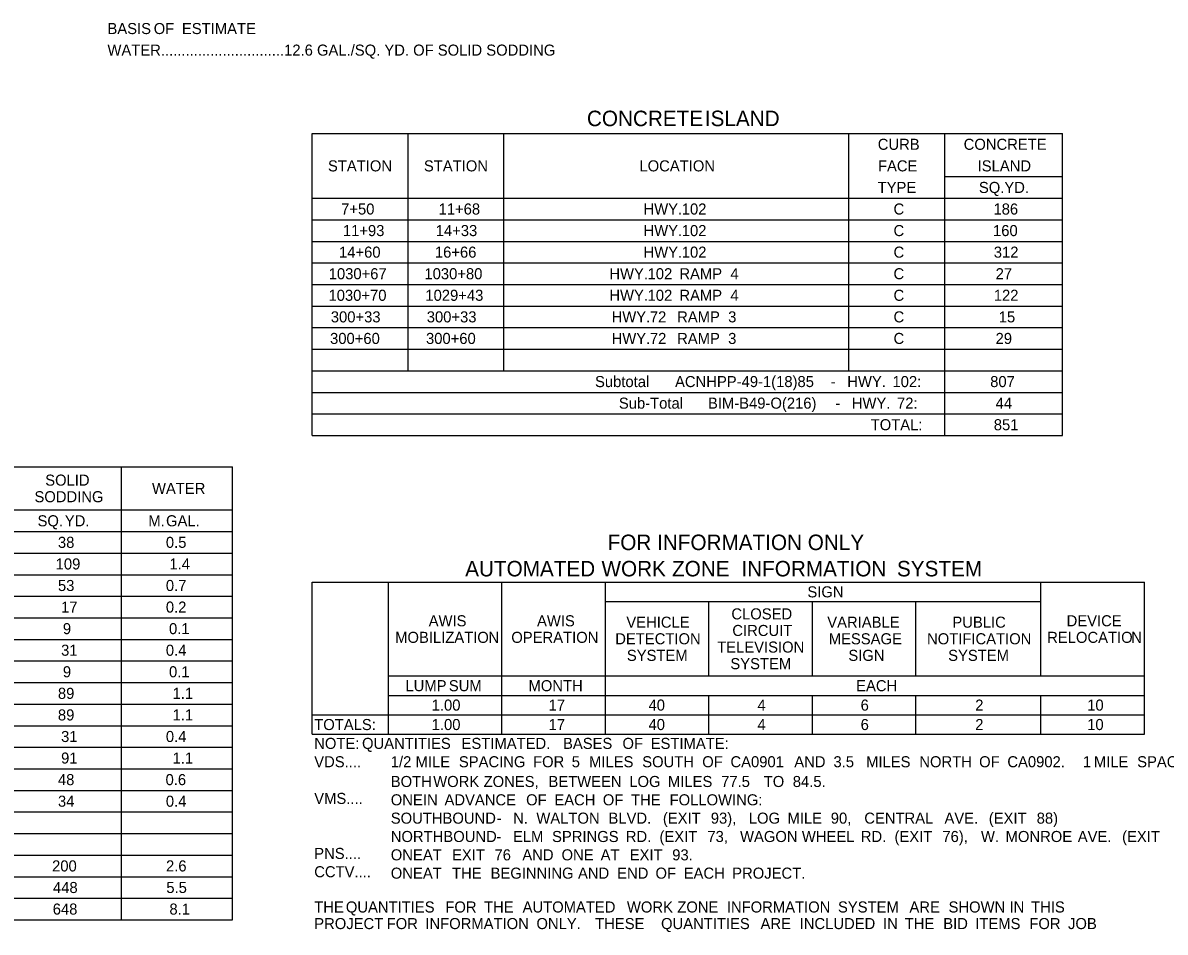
# Model space of a CAD drawing. Extents: x 1226605 to 1228152, y 151309 to 152316.
# Drawn here: x 1227104 to 1227621, y 151407 to 151818 of the extents above; entities that cross this region are included whole.
import ezdxf

# ---------------------------------------------------------------- set-up
doc = ezdxf.new("R2010")
doc.units = 0
doc.layers.add('R_Dimension', color=7, linetype='Continuous')

msp = doc.modelspace()

# ---------------------------------------------------------------- linework, layer by layer
at = {"layer": 'R_Dimension'}
for p, q in [((1227234.9, 151767.85), (1227574.2, 151767.85)), ((1227234.9, 151631.35), (1227234.9, 151767.85)), ((1227278.28, 151660.6), (1227278.28, 151767.85)), ((1227321.67, 151660.6), (1227321.67, 151767.85)), ((1227477.67, 151660.6), (1227477.67, 151767.85)), ((1227521.06, 151631.35), (1227521.06, 151767.85)), ((1227574.2, 151631.35), (1227574.2, 151767.85)), ((1227521.06, 151748.35), (1227574.2, 151748.35)), ((1227234.9, 151738.6), (1227574.2, 151738.6)), ((1227234.9, 151728.85), (1227574.2, 151728.85)), ((1227234.9, 151719.1), (1227574.2, 151719.1)), ((1227234.9, 151709.35), (1227574.2, 151709.35)), ((1227234.9, 151699.6), (1227574.2, 151699.6)), ((1227234.9, 151689.85), (1227574.2, 151689.85)), ((1227234.9, 151680.1), (1227574.2, 151680.1)), ((1227234.9, 151670.35), (1227574.2, 151670.35)), ((1227234.9, 151660.6), (1227574.2, 151660.6)), ((1227234.9, 151650.85), (1227574.2, 151650.85)), ((1227234.9, 151641.1), (1227574.2, 151641.1)), ((1227234.9, 151631.35), (1227574.2, 151631.35)), ((1226605.2, 151617.18), (1227198.97, 151617.18)), ((1227148.76, 151412.43), (1227148.76, 151617.18)), ((1227198.97, 151412.43), (1227198.97, 151617.18)), ((1226844.56, 151597.68), (1227198.97, 151597.68)), ((1227098.55, 151597.68), (1227198.97, 151597.68)), ((1226605.2, 151587.93), (1227198.97, 151587.93)), ((1226605.2, 151578.18), (1227198.97, 151578.18)), ((1226605.2, 151568.43), (1227198.97, 151568.43)), ((1227234.9, 151565.06), (1227611.25, 151565.06)), ((1227234.9, 151496.33), (1227234.9, 151565.06)), ((1227269.51, 151496.33), (1227269.51, 151565.06)), ((1227320.7, 151496.33), (1227320.7, 151565.06)), ((1227367.5, 151496.33), (1227367.5, 151565.06)), ((1227564.45, 151522.65), (1227564.45, 151565.06)), ((1227611.25, 151496.33), (1227611.25, 151565.06)), ((1226605.2, 151558.68), (1227198.97, 151558.68)), ((1227367.5, 151556.29), (1227564.45, 151556.29)), ((1227414.3, 151522.65), (1227414.3, 151556.29)), ((1227461.1, 151522.65), (1227461.1, 151556.29)), ((1227507.9, 151522.65), (1227507.9, 151556.29)), ((1226605.2, 151548.93), (1227198.97, 151548.93)), ((1226605.2, 151539.18), (1227198.97, 151539.18)), ((1226605.2, 151529.43), (1227198.97, 151529.43)), ((1227269.51, 151522.65), (1227611.25, 151522.65)), ((1227564.45, 151522.65), (1227611.25, 151522.65)), ((1226605.2, 151519.68), (1227198.97, 151519.68)), ((1227269.51, 151513.88), (1227611.25, 151513.88)), ((1227414.3, 151496.33), (1227414.3, 151513.88)), ((1227461.1, 151496.33), (1227461.1, 151513.88)), ((1227507.9, 151496.33), (1227507.9, 151513.88)), ((1227564.45, 151496.33), (1227564.45, 151513.88)), ((1226605.2, 151509.93), (1227198.97, 151509.93)), ((1227234.9, 151505.1), (1227611.25, 151505.1)), ((1226605.2, 151500.18), (1227198.97, 151500.18)), ((1227234.9, 151496.33), (1227611.25, 151496.33)), ((1226605.2, 151490.43), (1227198.97, 151490.43)), ((1226605.2, 151480.68), (1227198.97, 151480.68)), ((1226605.2, 151470.93), (1227198.97, 151470.93)), ((1226605.2, 151461.18), (1227198.97, 151461.18)), ((1226605.2, 151451.43), (1227198.97, 151451.43)), ((1226605.2, 151441.68), (1227198.97, 151441.68)), ((1226605.2, 151431.93), (1227198.97, 151431.93)), ((1226605.2, 151422.18), (1227198.97, 151422.18)), ((1226605.2, 151412.43), (1227198.97, 151412.43))]:
    msp.add_line(p, q, dxfattribs=at)

# ---------------------------------------------------------------- texts
for s, height, p in [('BASIS', 5, (1227142.38, 151812.79)), (' OF', 5, (1227161.44, 151812.79)), (' ESTIMATE', 5, (1227174.19, 151812.79)), ('WATER..............................12.6 GAL./SQ. YD. OF SOLID SODDING', 5, (1227142.38, 151803.04)), ('CONCRETE', 7, (1227359.18, 151771.17)), (' ISLAND', 7, (1227409.89, 151771.17)), ('CURB', 5, (1227490.68, 151760.47)), ('CONCRETE', 5, (1227529.52, 151760.47)), ('STATION', 5, (1227242.08, 151750.72)), ('STATION', 5, (1227285.47, 151750.72)), ('LOCATION', 5, (1227382.92, 151750.72)), ('FACE', 5, (1227490.78, 151750.72)), ('ISLAND', 5, (1227535.84, 151750.72)), ('TYPE', 5, (1227490.62, 151740.97)), ('SQ.YD.', 5, (1227536.41, 151740.97)), ('7+50', 5, (1227248.03, 151731.22)), ('11+68', 5, (1227292.1, 151731.22)), ('HWY.', 5, (1227384.77, 151731.22)), (' 102', 5, (1227400.2, 151731.22)), ('C', 5, (1227497.81, 151731.22)), ('186', 5, (1227543, 151731.22)), ('11+93', 5, (1227248.83, 151721.47)), ('14+33', 5, (1227290.8, 151721.47)), ('HWY.', 5, (1227384.77, 151721.47)), (' 102', 5, (1227400.2, 151721.47)), ('C', 5, (1227497.81, 151721.47)), ('160', 5, (1227542.8, 151721.47)), ('14+60', 5, (1227247.08, 151711.72)), ('16+66', 5, (1227290.43, 151711.72)), ('HWY.', 5, (1227384.77, 151711.72)), (' 102', 5, (1227400.2, 151711.72)), ('C', 5, (1227497.81, 151711.72)), ('312', 5, (1227543.14, 151711.72)), ('1030+67', 5, (1227242.42, 151701.97)), ('1030+80', 5, (1227285.7, 151701.97)), ('HWY.', 5, (1227369.32, 151701.97)), (' 102', 5, (1227384.75, 151701.97)), (' RAMP', 5, (1227399.12, 151701.97)), (' 4', 5, (1227422.19, 151701.97)), ('C', 5, (1227497.81, 151701.97)), ('27', 5, (1227543.97, 151701.97)), ('1030+70', 5, (1227242.32, 151692.22)), ('1029+43', 5, (1227286.12, 151692.22)), ('HWY.', 5, (1227369.32, 151692.22)), (' 102', 5, (1227384.75, 151692.22)), (' RAMP', 5, (1227399.12, 151692.22)), (' 4', 5, (1227422.19, 151692.22)), ('C', 5, (1227497.81, 151692.22)), ('122', 5, (1227543.14, 151692.22)), ('300+33', 5, (1227243.36, 151682.47)), ('300+33', 5, (1227286.75, 151682.47)), (' 72', 5, (1227385.77, 151682.47)), (' 3', 5, (1227421.17, 151682.47)), ('C', 5, (1227497.81, 151682.47)), ('HWY.', 5, (1227370.34, 151682.47)), (' RAMP', 5, (1227398.1, 151682.47)), ('15', 5, (1227545.38, 151682.47)), ('300+60', 5, (1227243.03, 151672.72)), ('300+60', 5, (1227286.41, 151672.72)), ('HWY.', 5, (1227370.34, 151672.72)), (' 72', 5, (1227385.77, 151672.72)), (' RAMP', 5, (1227398.1, 151672.72)), (' 3', 5, (1227421.17, 151672.72)), ('C', 5, (1227497.81, 151672.72)), ('29', 5, (1227543.95, 151672.72)), ('Subtotal', 5, (1227362.83, 151653.22)), (' ACNHPP-49-1(18)85', 5, (1227397.16, 151653.22)), (' HWY.', 5, (1227475.04, 151653.22)), (' 102:', 5, (1227495.47, 151653.22)), ('807', 5, (1227541.52, 151653.22)), (' -', 5, (1227467.6, 151653.22)), ('Sub-Total', 5, (1227373.62, 151643.47)), (' BIM-B49-O(216)', 5, (1227412.05, 151643.47)), (' HWY.', 5, (1227477.09, 151643.47)), (' 72:', 5, (1227497.52, 151643.47)), ('44', 5, (1227543.97, 151643.47)), (' -', 5, (1227469.64, 151643.47)), ('TOTAL:', 5, (1227487.48, 151633.72)), ('851', 5, (1227543.14, 151633.72)), ('SOLID', 5, (1227114.23, 151608.68)), ('SODDING', 5, (1227109.38, 151601.18)), ('WATER', 5, (1227162.51, 151604.93)), ('SQ.', 5, (1227110.76, 151590.3)), (' YD.', 5, (1227121.23, 151590.3)), ('M.', 5, (1227160.86, 151590.3)), (' GAL.', 5, (1227167, 151590.3)), ('38', 5, (1227119.99, 151580.55)), ('0.5', 5, (1227168.79, 151580.55)), ('FOR INFORMATION ONLY', 7, (1227368.54, 151579.55)), ('109', 5, (1227118.95, 151570.8)), ('1.4', 5, (1227170.4, 151570.8)), ('AUTOMATED', 7, (1227304.13, 151567.66)), (' WORK', 7, (1227363.16, 151567.66)), (' ZONE', 7, (1227395.07, 151567.66)), (' INFORMATION', 7, (1227426.43, 151567.66)), (' SYSTEM', 7, (1227496.76, 151567.66)), ('53', 5, (1227119.99, 151561.05)), ('0.7', 5, (1227168.79, 151561.05)), ('SIGN', 5, (1227458.86, 151558.18)), ('17', 5, (1227121.41, 151551.3)), ('0.2', 5, (1227168.79, 151551.3)), ('CLOSED', 5, (1227424.49, 151548.22)), ('AWIS', 5, (1227287.62, 151545.11)), ('AWIS', 5, (1227336.61, 151545.11)), ('VEHICLE', 5, (1227377, 151544.47)), ('VARIABLE', 5, (1227467.84, 151544.47)), ('PUBLIC', 5, (1227524.42, 151544.47)), ('DEVICE', 5, (1227576.07, 151545.11)), ('9', 5, (1227122.22, 151541.55)), ('0.1', 5, (1227170.21, 151541.55)), ('CIRCUIT', 5, (1227424.92, 151540.72)), ('MOBILIZATIO', 5, (1227272.46, 151537.61)), ('N', 5, (1227314.63, 151537.61)), ('OPERATION', 5, (1227324.98, 151537.61)), ('DETECTION', 5, (1227371.98, 151536.97)), ('TELEVISION', 5, (1227418.07, 151533.22)), ('MESSAGE', 5, (1227468.51, 151536.97)), ('NOTIFICATION', 5, (1227512.96, 151536.97)), ('RELOCATIO', 5, (1227567.29, 151537.61)), ('N', 5, (1227605.29, 151537.61)), ('31', 5, (1227121.41, 151531.8)), ('0.4', 5, (1227168.79, 151531.8)), ('SYSTEM', 5, (1227377.23, 151529.47)), ('SIGN', 5, (1227477.39, 151529.47)), ('SYSTEM', 5, (1227522.51, 151529.47)), ('SYSTEM', 5, (1227424.03, 151525.72)), ('9', 5, (1227122.22, 151522.05)), ('0.1', 5, (1227170.21, 151522.05)), ('89', 5, (1227119.97, 151512.3)), ('1.1', 5, (1227171.82, 151512.3)), ('LUMP', 5, (1227277.11, 151515.76)), (' SUM', 5, (1227294.87, 151515.76)), ('MONTH', 5, (1227332.76, 151515.76)), ('EACH', 5, (1227480.91, 151515.76)), ('1.00', 5, (1227288.98, 151506.99)), ('17', 5, (1227341.85, 151506.99)), ('40', 5, (1227387.02, 151506.99)), ('4', 5, (1227436.28, 151506.99)), ('6', 5, (1227482.94, 151506.99)), ('2', 5, (1227534.75, 151506.99)), ('10', 5, (1227585.38, 151506.99)), ('89', 5, (1227119.97, 151502.55)), ('1.1', 5, (1227171.82, 151502.55)), ('TOTALS:', 5, (1227235.87, 151498.21)), ('1.00', 5, (1227288.98, 151498.21)), ('17', 5, (1227341.85, 151498.21)), ('40', 5, (1227387.02, 151498.21)), ('4', 5, (1227436.28, 151498.21)), ('6', 5, (1227482.94, 151498.21)), ('2', 5, (1227534.75, 151498.21)), ('10', 5, (1227585.38, 151498.21)), ('31', 5, (1227121.41, 151492.8)), ('0.4', 5, (1227168.79, 151492.8)), ('NOTE:', 5, (1227235.87, 151489.68)), (' QUANTITIES', 5, (1227255.63, 151489.68)), (' ESTIMATED.', 5, (1227300.63, 151489.68)), (' BASES', 5, (1227346.5, 151489.68)), (' OF', 5, (1227373.39, 151489.68)), (' ESTIMATE:', 5, (1227386.15, 151489.68)), ('91', 5, (1227121.41, 151483.05)), ('1.1', 5, (1227171.82, 151483.05)), ('VDS....', 5, (1227235.87, 151481.39)), ('1/2', 5, (1227270.48, 151481.39)), (' MILE', 5, (1227279.85, 151481.39)), (' SPACING', 5, (1227299.42, 151481.39)), (' FOR', 5, (1227332.96, 151481.39)), (' 5', 5, (1227350.44, 151481.39)), (' MILES', 5, (1227358.28, 151481.39)), (' SOUTH', 5, (1227382.33, 151481.39)), (' OF', 5, (1227409.46, 151481.39)), (' CA0901', 5, (1227422.22, 151481.39)), (' AND', 5, (1227451.07, 151481.39)), (' 3.5', 5, (1227468.79, 151481.39)), (' MILES', 5, (1227483.55, 151481.39)), (' NORTH', 5, (1227507.61, 151481.39)), (' OF', 5, (1227534.66, 151481.39)), (' CA0902.', 5, (1227547.41, 151481.39)), (' 1', 5, (1227581.55, 151481.39)), (' MILE', 5, (1227586.55, 151481.39)), (' SPACING', 5, (1227606.11, 151481.39)), ('48', 5, (1227119.99, 151473.3)), ('0.6', 5, (1227168.65, 151473.3)), ('BOTH', 5, (1227270.48, 151472.46)), (' WORK', 5, (1227287.81, 151472.46)), (' ZONES,', 5, (1227310.6, 151472.46)), (' BETWEEN', 5, (1227339.93, 151472.46)), (' LOG', 5, (1227376.47, 151472.46)), (' MILES', 5, (1227393.95, 151472.46)), (' 77.5', 5, (1227418, 151472.46)), (' TO', 5, (1227437.25, 151472.46)), (' 84.5.', 5, (1227450.4, 151472.46)), ('34', 5, (1227119.99, 151463.55)), ('0.4', 5, (1227168.79, 151463.55)), ('VMS....', 5, (1227235.87, 151464.82)), ('ONE', 5, (1227270.48, 151464.18)), (' IN', 5, (1227283.16, 151464.18)), (' ADVANCE', 5, (1227292.92, 151464.18)), (' OF', 5, (1227329.81, 151464.18)), (' EACH', 5, (1227342.57, 151464.18)), (' OF', 5, (1227364.5, 151464.18)), (' THE', 5, (1227377.25, 151464.18)), (' FOLLOWING:', 5, (1227394.7, 151464.18)), ('SOUTHBOUND', 5, (1227270.48, 151455.89)), (' N.', 5, (1227323.95, 151455.89)), (' WALTON', 5, (1227334.46, 151455.89)), (' BLVD.', 5, (1227367.06, 151455.89)), (' (EXIT', 5, (1227391.66, 151455.89)), (' 93),', 5, (1227413.32, 151455.89)), (' LOG', 5, (1227430.52, 151455.89)), (' MILE', 5, (1227448, 151455.89)), (' 90,', 5, (1227467.57, 151455.89)), (' CENTRAL', 5, (1227482.73, 151455.89)), (' AVE.', 5, (1227518.99, 151455.89)), (' (EXIT', 5, (1227539.03, 151455.89)), (' 88)', 5, (1227560.68, 151455.89)), (' -', 5, (1227316.51, 151455.89)), ('NORTHBOUND', 5, (1227270.48, 151447.6)), (' ELM', 5, (1227323.87, 151447.6)), (' SPRINGS', 5, (1227341.55, 151447.6)), (' RD.', 5, (1227374.89, 151447.6)), (' (EXIT', 5, (1227390.13, 151447.6)), (' 73,', 5, (1227411.78, 151447.6)), (' WAGON', 5, (1227426.55, 151447.6)), (' WHEEL', 5, (1227454.5, 151447.6)), (' RD.', 5, (1227481.15, 151447.6)), (' (EXIT', 5, (1227496.39, 151447.6)), (' 76),', 5, (1227518.04, 151447.6)), (' W.', 5, (1227535.48, 151447.6)), (' MONROE', 5, (1227546.62, 151447.6)), (' AVE.', 5, (1227579.26, 151447.6)), (' (EXIT', 5, (1227599.3, 151447.6)), ('PNS....', 5, (1227235.87, 151439.96)), (' -', 5, (1227316.43, 151447.6)), ('ONE', 5, (1227270.48, 151439.31)), (' AT', 5, (1227283.16, 151439.31)), (' EXIT', 5, (1227296.31, 151439.31)), (' 76', 5, (1227315.52, 151439.31)), (' AND', 5, (1227328.12, 151439.31)), (' ONE', 5, (1227345.84, 151439.31)), (' AT', 5, (1227363.51, 151439.31)), (' EXIT', 5, (1227376.66, 151439.31)), (' 93.', 5, (1227395.88, 151439.31)), ('200', 5, (1227117.34, 151434.3)), ('2.6', 5, (1227168.85, 151434.3)), ('CCTV....', 5, (1227235.87, 151431.67)), ('ONE', 5, (1227270.48, 151431.03)), (' AT', 5, (1227283.16, 151431.03)), (' THE', 5, (1227296.31, 151431.03)), (' BEGINNING', 5, (1227313.75, 151431.03)), (' AND', 5, (1227353.28, 151431.03)), (' END', 5, (1227370.99, 151431.03)), (' OF', 5, (1227388.32, 151431.03)), (' EACH', 5, (1227401.07, 151431.03)), (' PROJECT.', 5, (1227423, 151431.03)), ('448', 5, (1227117.75, 151424.55)), ('5.5', 5, (1227168.99, 151424.55)), ('648', 5, (1227117.63, 151414.8)), ('8.1', 5, (1227170.4, 151414.8)), ('THE', 5, (1227235.87, 151415.74)), (' QUANTITIES', 5, (1227248.31, 151415.74)), (' FOR', 5, (1227293.31, 151415.74)), (' THE', 5, (1227310.79, 151415.74)), (' AUTOMATED', 5, (1227328.23, 151415.74)), (' WORK', 5, (1227375.4, 151415.74)), (' ZONE', 5, (1227398.19, 151415.74)), (' INFORMATION', 5, (1227420.59, 151415.74)), (' SYSTEM', 5, (1227470.83, 151415.74)), (' ARE', 5, (1227503.15, 151415.74)), (' SHOWN', 5, (1227520.83, 151415.74)), (' IN', 5, (1227548.39, 151415.74)), (' THIS', 5, (1227558.15, 151415.74)), ('PROJECT', 5, (1227235.87, 151408.24)), (' FOR', 5, (1227266.78, 151408.24)), (' INFORMATION', 5, (1227284.26, 151408.24)), (' ONLY.', 5, (1227334.49, 151408.24)), ('  THESE', 5, (1227359.18, 151408.24)), (' QUANTITIES', 5, (1227390.83, 151408.24)), (' ARE', 5, (1227435.83, 151408.24)), (' INCLUDED', 5, (1227453.51, 151408.24)), (' IN', 5, (1227491.22, 151408.24)), (' THE', 5, (1227500.99, 151408.24)), (' BID', 5, (1227518.43, 151408.24)), (' ITEMS', 5, (1227532.92, 151408.24)), (' FOR', 5, (1227557.37, 151408.24)), (' JOB', 5, (1227574.85, 151408.24))]:
    msp.add_text(s, height=height, dxfattribs=at).set_placement(p)

doc.saveas('drawing.dxf')
